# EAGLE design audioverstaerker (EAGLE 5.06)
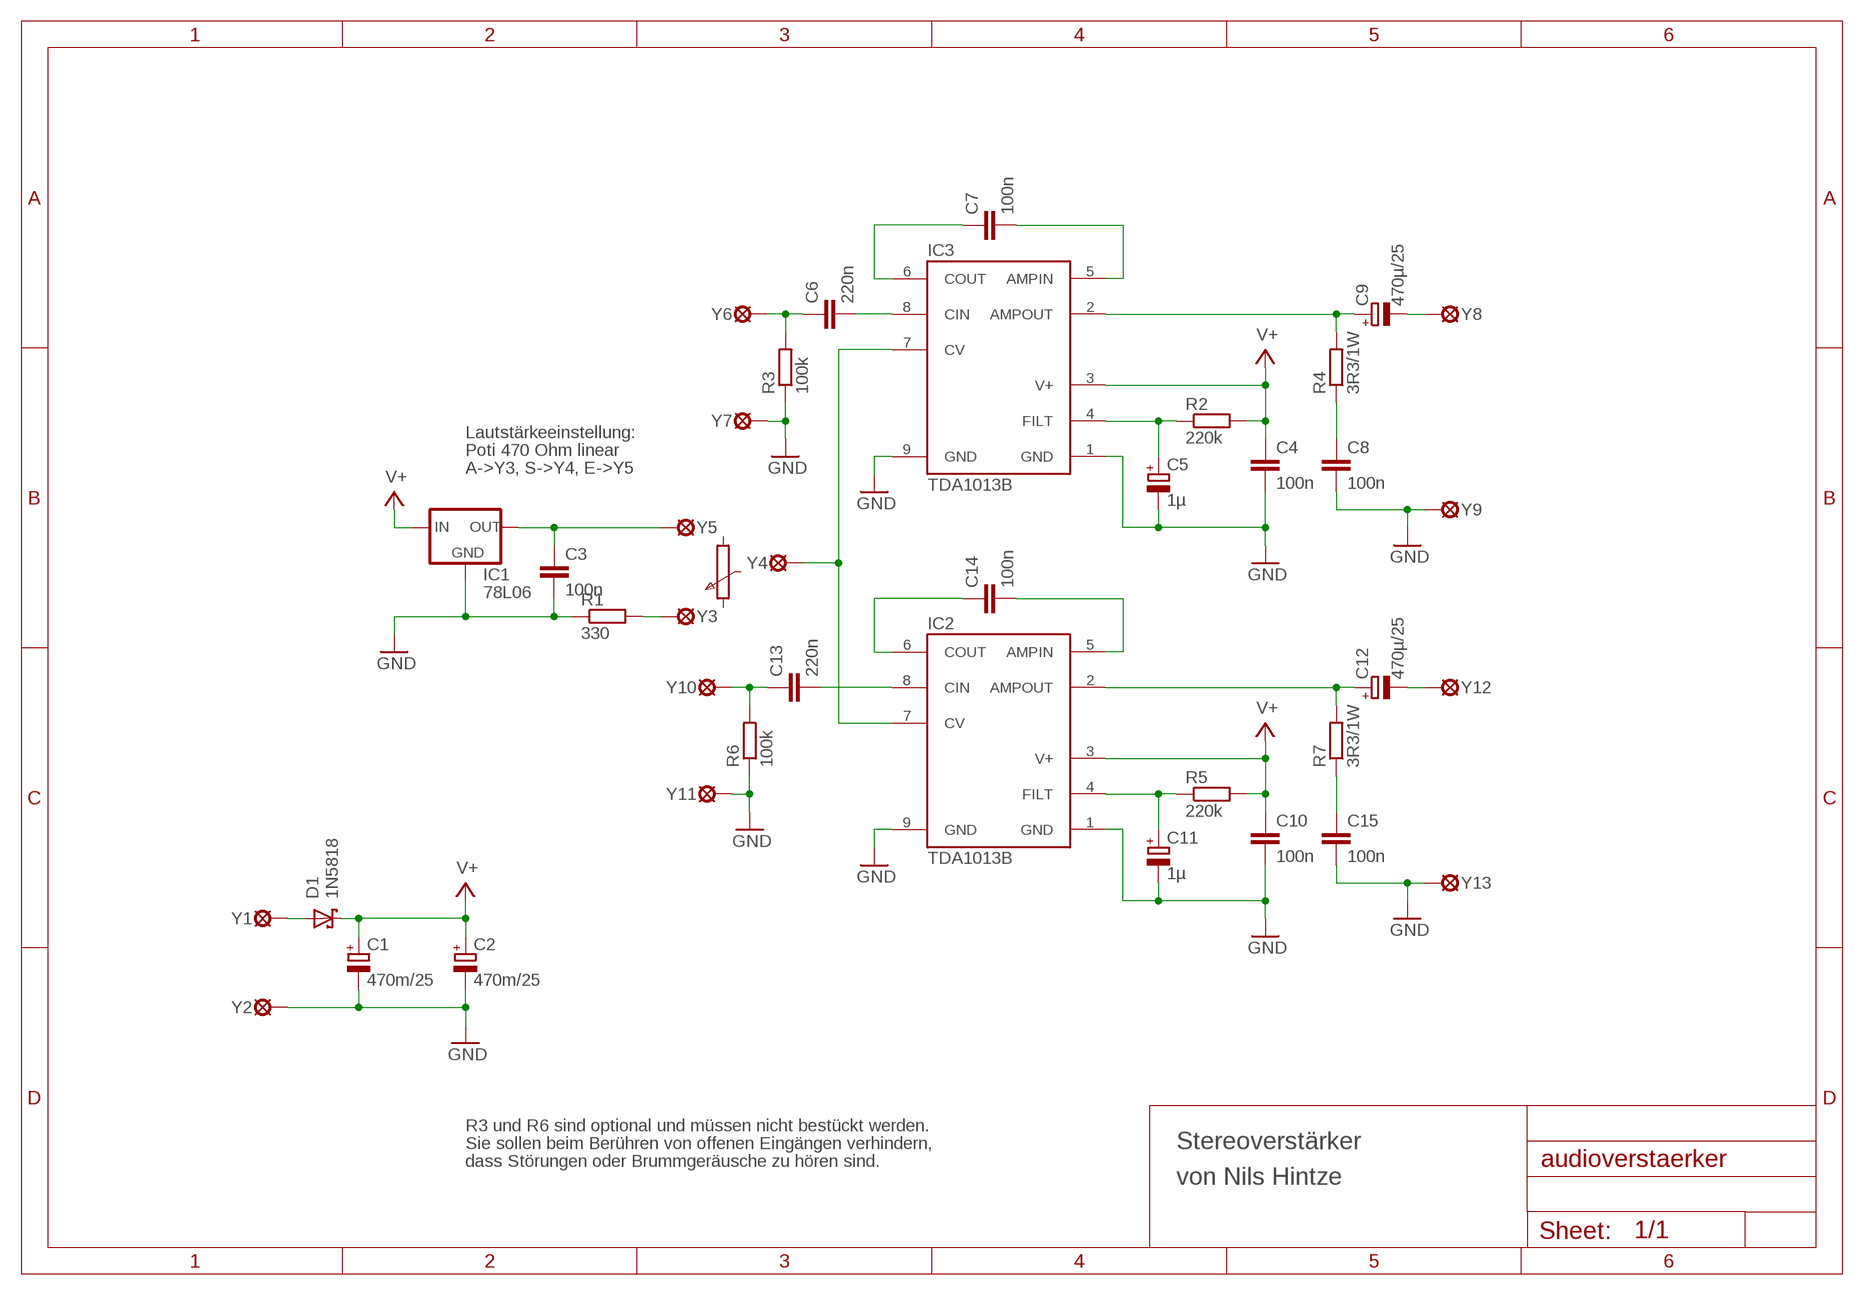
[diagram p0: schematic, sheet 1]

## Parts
C1  470m/25  CPOL-EUE5-10.5  [E5-10,5]
C2  470m/25  CPOL-EUE5-10.5  [E5-10,5]
C3  100n  C-EU025-024X044  [C025-024X044]
C4  100n  C-EU050-024X044  [C050-024X044]
C5  1µ  CPOL-EUE2.5-6  [E2,5-6]
C6  220n  C-EU050-045X075  [C050-045X075]
C7  100n  C-EU050-025X075  [C050-025X075]
C8  100n  C-EU050-025X075  [C050-025X075]
C9  470µ/25  CPOL-EUE5-10.5  [E5-10,5]
C10  100n  C-EU050-024X044  [C050-024X044]
C11  1µ  CPOL-EUE2.5-6  [E2,5-6]
C12  470µ/25  CPOL-EUE5-10.5  [E5-10,5]
C13  220n  C-EU050-045X075  [C050-045X075]
C14  100n  C-EU050-025X075  [C050-025X075]
C15  100n  C-EU050-025X075  [C050-025X075]
D1  1N5818  SCHOTTKY-DIODEDO41-10  [DO41-10]
IC1  78L06  78LXX-  [TO92-]
IC2  TDA1013B  [SIL9MPF]
IC3  TDA1013B  [SIL9MPF]
R1  330  R-EU_0207/10  [0207/10]
R2  220k  R-EU_0207/10  [0207/10]
R3  100k  R-EU_0207/7  [0207/7]
R4  3R3/1W  R-EU_0309/V  [0309V]
R5  220k  R-EU_0207/10  [0207/10]
R6  100k  R-EU_0207/7  [0207/7]
R7  3R3/1W  R-EU_0309/V  [0309V]
Y1  MCS10B  [MCS10B]
Y2  MCS10B  [MCS10B]
Y3  MCS10B  [MCS10B]
Y4  MCS10B  [MCS10B]
Y5  MCS10B  [MCS10B]
Y6  MCS10B  [MCS10B]
Y7  MCS10B  [MCS10B]
Y8  MCS10B  [MCS10B]
Y9  MCS10B  [MCS10B]
Y10  MCS10B  [MCS10B]
Y11  MCS10B  [MCS10B]
Y12  MCS10B  [MCS10B]
Y13  MCS10B  [MCS10B]

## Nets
GND: C1.- C2.- C3.2 C4.2 C5.- C8.2 C10.2 C11.- C15.2 IC1.2(GND) IC2.1(GND) IC2.9(GND) IC3.1(GND) IC3.9(GND) R1.1 R3.1 R6.1 Y2.MP Y7.MP Y9.MP Y11.MP Y13.MP
N$1: C3.1 IC1.3(OUT) Y5.MP
N$3: R1.2 Y3.MP
N$4: D1.A Y1.MP
N$5: C5.+ IC3.4(FILT) R2.1
N$6: C9.+ IC3.2(AMPOUT) R4.2
N$7: C7.1 IC3.6(COUT)
N$8: C7.2 IC3.5(AMPIN)
N$9: C6.2 IC3.8(CIN)
N$10: C6.1 R3.2 Y6.MP
N$11: IC2.7(CV) IC3.7(CV) Y4.MP
N$12: C8.1 R4.1
N$13: C11.+ IC2.4(FILT) R5.1
N$14: C9.- Y8.MP
N$15: C12.+ IC2.2(AMPOUT) R7.2
N$16: C14.1 IC2.6(COUT)
N$17: C14.2 IC2.5(AMPIN)
N$18: C13.2 IC2.8(CIN)
N$19: C13.1 R6.2 Y10.MP
N$21: C15.1 R7.1
N$22: C12.- Y12.MP
V+: C1.+ C2.+ C4.1 C10.1 D1.C IC1.1(IN) IC2.3(V+) IC3.3(V+) R2.2 R5.2

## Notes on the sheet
- Lautstärkeeinstellung:
- Poti 470 Ohm linear
- A->Y3, S->Y4, E->Y5
- R3 und R6 sind optional und müssen nicht bestückt werden.
- Sie sollen beim Berühren von offenen Eingängen verhindern, | Stereoverstärker
- dass Störungen oder Brummgeräusche zu hören sind.
- von Nils Hintze

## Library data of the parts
C1 C2 C5 C9 C11 C12 = nh_rcl:CPOL-EU: POLARIZED CAPACITOR, European symbol
C3 C4 C6-C8 C10 C13-C15 = nh_rcl:C-EU: CAPACITOR, European symbol
D1 = nh_diode:SCHOTTKY-DIODE: Schottky Diode
IC1 = nh_v-reg:78LXX: VOLTAGE REGULATOR
IC2 IC3 = nh_tda1013b:TDA1013B
R1-R7 = nh_rcl:R-EU_: RESISTOR, European symbol
Y1-Y13 = solpad:MCS10B: SOLDER PAD

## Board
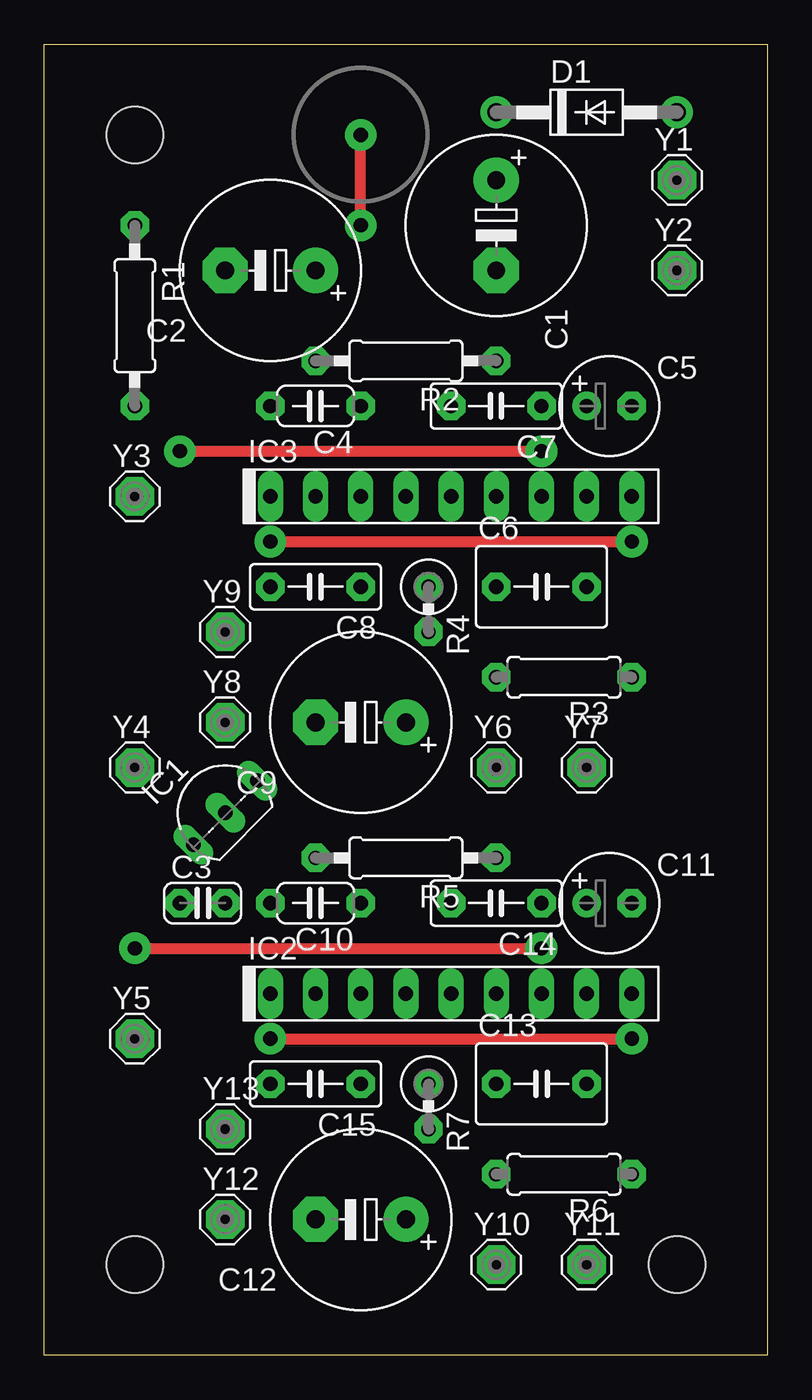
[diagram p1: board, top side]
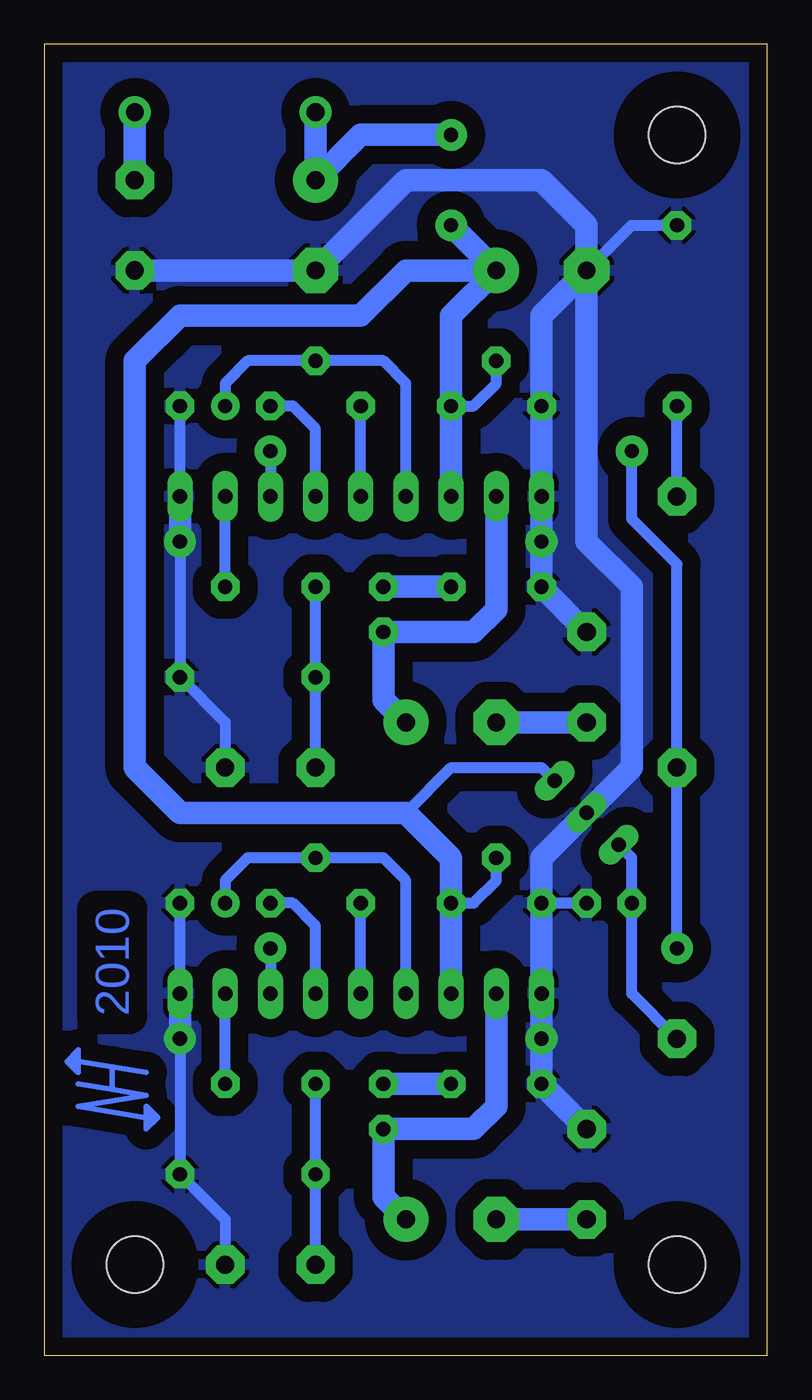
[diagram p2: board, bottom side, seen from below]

Size 40.64 x 73.66 mm. Coordinates in mm from the lower left corner, seen from the top.
Outline: 0,73.66 40.64,73.66 40.64,0 0,0 0,73.66
Copper layers (1*16): Top 0.035mm / dielectric 1.5mm / Bottom 0.035mm
Design rules "default": minimum track width 10mil, minimum drill 24mil, track to track 8mil, track to pad 8mil, pad to pad 8mil, via to via 8mil, smd to smd 8mil, copper to edge 40mil, drill to drill 8mil, minimum pad ring 10mil, minimum via ring 8mil, stop-mask expansion 4mil, vias tented up to drill 0mil, thermal gap 10mil
Holes 3.2 mm at 5.08,68.58 5.08,5.08 35.56,5.08
bRestrict: area 2.5,66 to 7.6,71.1; area 2.5,2.5 to 7.6,7.6; area 33,2.5 to 38.1,7.6

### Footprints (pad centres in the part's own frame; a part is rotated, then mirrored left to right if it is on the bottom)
E5-10,5 = drill 1 pad 2.54 round: + -2.54,0 | drill 1 pad 2.54 octagon: - 2.54,0
C025-024X044 = drill 0.8 pad 1.6 octagon: 1 -1.27,0; 2 1.27,0
C050-024X044 = drill 0.8 pad 1.6 octagon: 1 -2.54,0; 2 2.54,0
E2,5-6 = drill 0.8 pad 1.6 round: + -1.27,0 | drill 0.8 pad 1.6 octagon: - 1.27,0
C050-045X075 = drill 0.8 pad 1.6 octagon: 1 -2.54,0; 2 2.54,0
C050-025X075 = drill 0.8 pad 1.6 octagon: 1 -2.54,0; 2 2.54,0
DO41-10 = drill 1 pad 1.8 round: A 5.08,0; C -5.08,0
TO92- = drill 0.813 long: 1 2.54,0; 2 0,0; 3 -2.54,0
SIL9MPF = drill 0.813 pad 1.422 long: 1 -10.16,0; 2 -7.62,0; 3 -5.08,0; 4 -2.54,0; 5 0,0; 6 2.54,0; 7 5.08,0; 8 7.62,0; 9 10.16,0
0207/10 = drill 0.8 pad 1.6 octagon: 1 -5.08,0; 2 5.08,0
0207/7 = drill 0.8 pad 1.6 octagon: 1 -3.81,0; 2 3.81,0
0309V = drill 0.8 pad 1.6 octagon: 1 -1.27,0; 2 1.27,0
MCS10B = drill 1.016 pad 2.159 octagon: MP 0,0

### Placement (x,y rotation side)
C1  25.4,63.5 270 top
C2  12.7,60.96 180 top
C3  8.89,25.4 0 top
C4  15.24,53.34 180 top
C5  31.75,53.34 0 top
C6  27.94,43.18 0 top
C7  25.4,53.34 180 top
C8  15.24,43.18 180 top
C9  17.78,35.56 180 top
C10  15.24,25.4 180 top
C11  31.75,25.4 0 top
C12  17.78,7.62 180 top
C13  27.94,15.24 0 top
C14  25.4,25.4 180 top
C15  15.24,15.24 180 top
D1  30.48,69.85 0 top
IC1  10.16,30.48 45 top
IC2  22.86,20.32 0 top
IC3  22.86,48.26 0 top
R1  5.08,58.42 270 top
R2  20.32,55.88 180 top
R3  29.21,38.1 180 top
R4  21.59,41.91 270 top
R5  20.32,27.94 180 top
R6  29.21,10.16 180 top
R7  21.59,13.97 270 top
Y1  35.56,66.04 0 top
Y2  35.56,60.96 0 top
Y3  5.08,48.26 0 top
Y4  5.08,33.02 0 top
Y5  5.08,17.78 0 top
Y6  25.4,33.02 0 top
Y7  30.48,33.02 0 top
Y8  10.16,35.56 0 top
Y9  10.16,40.64 0 top
Y10  25.4,5.08 0 top
Y11  30.48,5.08 0 top
Y12  10.16,7.62 0 top
Y13  10.16,12.7 0 top

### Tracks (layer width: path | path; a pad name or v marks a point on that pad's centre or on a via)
GND  (via drill 0.8 pad 1.78)
  Top 0.61: v12.7,45.72 v33.02,45.72 | v12.7,17.78 v33.02,17.78
  Bottom 0.61: IC3.9 C5.- | v33.02,45.72 R3.1 30.48,35.56 Y7.MP | IC2.9 C11.- | Y11.MP 30.48,7.62 R6.1 v33.02,17.78 | C10.2 C3.2 | C2.- 7.62,63.5 R1.1
  Bottom 1.27: v33.02,45.72 IC3.9 | C2.- 12.7,58.42 C4.2 IC3.1 v12.7,45.72 C8.2 Y9.MP | Y13.MP C15.2 v12.7,17.78 IC2.1 C10.2 12.7,27.94 IC1.2 7.62,33.02 7.62,43.18 10.16,45.72 C2.- | v33.02,17.78 IC2.9 | Y2.MP C1.- 20.32,66.04 12.7,66.04 10.16,63.5 C2.-
  pour Bottom (isolate 1.016): 0,73.66 40.64,73.66 40.64,0 0,0
  pour Bottom (isolate 1.016): 0,73.66 40.64,73.66 40.64,0 0,0
N$1
  Bottom 0.61: IC1.3 7.62,27.94 C3.1 7.62,20.32 Y5.MP
N$3
  Bottom 0.61: Y3.MP R1.2
N$4
  Bottom 1.27: Y1.MP D1.A
N$5
  Bottom 0.61: C5.+ 30.48,54.61 29.21,55.88 R2.1 21.59,55.88 20.32,54.61 IC3.4
N$6
  Bottom 1.27: C9.+ 21.59,36.83 R4.2 16.51,40.64 15.24,41.91 IC3.2
N$7
  Bottom 0.61: C7.1 26.67,53.34 25.4,52.07 IC3.6
N$8
  Bottom 0.61: IC3.5 C7.2
N$9
  Bottom 0.61: C6.2 IC3.8
N$10
  Bottom 0.61: C6.1 R3.2 Y6.MP
N$11  (via drill 0.8 pad 1.78)
  Top 0.61: v7.62,50.8 v27.94,50.8 | v5.08,22.86 v27.94,22.86
  Bottom 0.61: v27.94,50.8 IC3.7 | v27.94,22.86 IC2.7 | v5.08,22.86 Y4.MP 5.08,44.45 7.62,46.99 v7.62,50.8
N$12
  Bottom 1.27: C8.1 R4.1
N$13
  Bottom 0.61: IC2.4 20.32,26.67 21.59,27.94 R5.1 29.21,27.94 30.48,26.67 C11.+
N$14
  Bottom 1.27: Y8.MP C9.-
N$15
  Bottom 1.27: C12.+ 21.59,8.89 R7.2 16.51,12.7 15.24,13.97 IC2.2
N$16
  Bottom 0.61: C14.1 26.67,25.4 25.4,24.13 IC2.6
N$17
  Bottom 0.61: IC2.5 C14.2
N$18
  Bottom 0.61: C13.2 IC2.8
N$19
  Bottom 0.61: C13.1 R6.2 Y10.MP
N$21
  Bottom 1.27: C15.1 R7.1
N$22
  Bottom 1.27: Y12.MP C12.-
N$23
  Bottom 0.305: 34.92,13.34 38.73,13.97 34.92,14.61 36.83,14.92 | 36.83,14.92 38.73,15.24 | 36.83,14.92 36.83,16.19 | 36.83,16.19 38.73,16.51 | 36.83,16.19 34.92,15.88 | 34.92,13.34 34.92,12.7 | 34.29,13.34 34.92,12.7 | 34.29,13.34 34.92,13.97 | 34.92,13.34 34.92,13.97 | 38.73,16.51 38.73,15.88 | 38.73,15.88 39.37,16.51 | 38.73,17.14 39.37,16.51 | 38.73,16.51 38.73,17.14 | 38.73,16.51 39.05,16.51 | 39.05,16.51 39.37,16.51 | 34.61,13.34 34.92,13.34 | 34.61,13.34 34.29,13.34 | 38.73,17.14 39.05,16.51 | 38.73,15.88 39.05,16.51 | 34.61,13.34 34.92,13.97 | 34.61,13.34 34.92,12.7
V+  (via drill 0.8 pad 1.78)
  Top 0.61: v17.78,63.5 v17.78,68.58
  Bottom 0.61: C4.1 16.51,53.34 15.24,54.61 R2.2 | R5.2 15.24,26.67 16.51,25.4 C10.1 | IC1.1 12.7,33.02 17.78,33.02 20.32,30.48
  Bottom 1.27: IC3.3 C4.1 17.78,58.42 C2.+ | IC2.3 C10.1 17.78,27.94 20.32,30.48 33.02,30.48 35.56,33.02 35.56,55.88 33.02,58.42 22.86,58.42 20.32,60.96 C2.+ | D1.C C1.+ 22.86,68.58 v17.78,68.58 | C2.+ v17.78,63.5

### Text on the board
Bottom: 2010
